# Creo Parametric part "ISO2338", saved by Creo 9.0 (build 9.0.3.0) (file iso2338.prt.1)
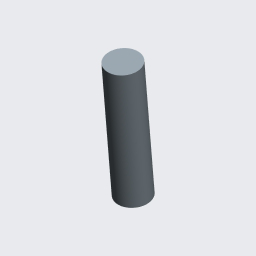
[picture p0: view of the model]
Units: Custom; MM, KILOGRAM, SECS

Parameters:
  BEZEICHNUNG = "ISO 2338-A-6x30-St"
  BENENNUNG = "Zylinderstift"
  INFO = "ungehaertet (iso 2338:1986)(EN 22338:1992)"
  MATERIAL = "Automatenstahl"
  ABMESSUNG = "generisch"
  NORM_HALBZEUG = "ISO 2338"

Other parameters: KATEGORIE, MASSE, D2, D3, D11

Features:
  1. datum plane "MITTE"
  2. chamfer
  3. datum plane "DTM1"
  4. cut
  5. chamfer

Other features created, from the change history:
  component interface "Komponentenschnittstelle ID 112"

Other named items: GEWICHT

Named dimensions: Laenge, Nenndurchmesser, Fasenhoehe, Kuppenhoehe

Layers: HILFEN, KONSTRUKTIONSELEMENTE

Family table entries: ISO2338A0_6X2, ISO2338, value(d_val), value(s_val), Zylinderstift A - 0.6 X 2, 3A - 0.6 X 2, )ISO 2338 - A - 0.6 X 2, value(i_val), ISO2338A0_6X3, ISO2338, )Zylinderstift A - 0.6 X 3, 3A - 0.6 X 3, )ISO 2338 - A - 0.6 X 3, ISO2338A0_6X4, ISO2338, )Zylinderstift A - 0.6 X 4, 3A - 0.6 X 4, )ISO 2338 - A - 0.6 X 4, ISO2338A0_6X5, ISO2338, )Zylinderstift A - 0.6 X 5, 3A - 0.6 X 5, )ISO 2338 - A - 0.6 X 5, ISO2338A0_6X6, ISO2338, )Zylinderstift A - 0.6 X 6, 3A - 0.6 X 6, )ISO 2338 - A - 0.6 X 6, ISO2338A0_8X2, ISO2338, )Zylinderstift A - 0.8 X 2, 3A - 0.8 X 2, )ISO 2338 - A - 0.8 X 2, ISO2338A0_8X3, ISO2338, )Zylinderstift A - 0.8 X 3, 3A - 0.8 X 3, )ISO 2338 - A - 0.8 X 3, ISO2338A0_8X4, ISO2338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

Surfaces: 2 plane, 2 cylinder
